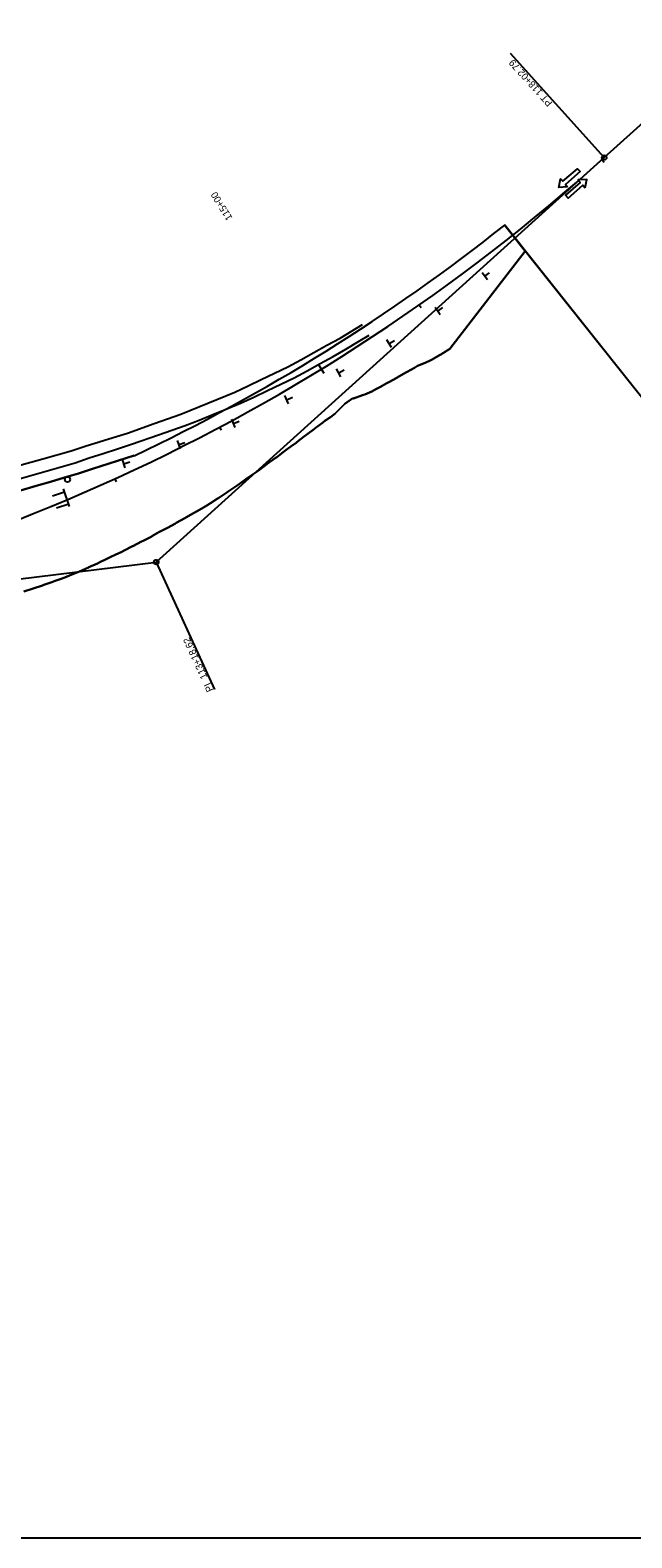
# Model space of a CAD drawing. Extents: x 1568809 to 1572786, y 728326 to 734907.
# Drawn here: x 1571487 to 1572002, y 731509 to 732799 of the extents above; entities that cross this region are included whole.
import ezdxf

# ---------------------------------------------------------------- set-up
doc = ezdxf.new("R2010")
doc.units = 0
for name, color, linetype in [('R_Horz Alg', 7, 'Continuous'), ('R_Horz Alg Annot', 7, 'Continuous'), ('R_MOT', 7, 'Continuous'), ('R_No Plot', 7, 'Continuous'), ('R_Striping', 7, 'Continuous')]:
    doc.layers.add(name, color=color, linetype=linetype)

msp = doc.modelspace()

# ---------------------------------------------------------------- linework, layer by layer
at = {"layer": 'R_Horz Alg'}
msp.add_line((1571978.5, 732690.3), (1572468.4, 733132.6), dxfattribs=at)
msp.add_arc((1570881.5, 733905.4), 1637, 277.05, 312.0749, dxfattribs=at)
at = {"layer": 'R_Horz Alg Annot'}
for p, q in [((1571595, 732344.1), (1571978.5, 732690.3)), ((1571082.4, 732280.7), (1571595, 732344.1))]:
    msp.add_line(p, q, dxfattribs=at)
for points in [[(1571978.5, 732690.3), (1571898.1, 732779.3)], [(1571978.4, 732686.2), (1571976.4, 732688.4)], [(1571901.9, 732621.5), (1571900.1, 732623.8)], [(1571821.6, 732561.6), (1571819.9, 732564)], [(1571734.2, 732512.7), (1571738.4, 732505.8)], [(1571650.9, 732457), (1571649.5, 732459.7)], [(1571561, 732412.8), (1571559.8, 732415.5)], [(1571595, 732344.1), (1571644.9, 732235)]]:
    msp.add_lwpolyline(points, dxfattribs=at)
for centre in [(1571978.5, 732690.3), (1571595, 732344.1)]:
    msp.add_circle(centre, 2, dxfattribs=at)
at = {"layer": 'R_MOT'}
for p, q in [((1571878.4, 732585.6), (1571873.8, 732591.7)), ((1571876.2, 732588.7), (1571880.3, 732591.8)), ((1571838, 732555.8), (1571833.6, 732562.1)), ((1571835.9, 732559), (1571840.2, 732562)), ((1571796.3, 732527.9), (1571792.3, 732534.4)), ((1571794.4, 732531.2), (1571798.9, 732533.9)), ((1571752.9, 732502.7), (1571749.3, 732509.4)), ((1571751.2, 732506.1), (1571755.8, 732508.6)), ((1571708.3, 732479.6), (1571705.1, 732486.6)), ((1571706.8, 732483.1), (1571711.5, 732485.3)), ((1571662.5, 732459.2), (1571659.6, 732466.3)), ((1571661.1, 732462.7), (1571666, 732464.7)), ((1571615.7, 732441), (1571613.2, 732448.2)), ((1571614.5, 732444.7), (1571619.5, 732446.4)), ((1571568.3, 732424.7), (1571566, 732431.9)), ((1571567.3, 732428.3), (1571572.3, 732429.9)), ((1571520.8, 732391.6), (1571515.7, 732406.7)), ((1571506.2, 732400.8), (1571516.5, 732404.3)), ((1571509.7, 732390.6), (1571520, 732394.1))]:
    msp.add_line(p, q, dxfattribs=at)
for points in [[(1571947, 732665.3), (1571939.7, 732664.8), (1571941.1, 732672.1), (1571943, 732670), (1571955.5, 732680.8), (1571957.7, 732678.3), (1571945.2, 732667.4)], [(1571962, 732664.5), (1571963.4, 732671.7), (1571956, 732671.2), (1571957.9, 732669.1), (1571945.4, 732658.3), (1571947.6, 732655.7), (1571960.1, 732666.6)]]:
    msp.add_lwpolyline(points, close=True, dxfattribs=at)
msp.add_circle((1571519, 732414.9), 2.25, dxfattribs=at)
at = {"layer": 'R_No Plot'}
for p, q in [((1572786.1, 731508.9), (1571892.9, 732632.9)), ((1572786.1, 731508.9), (1571893.2, 732632.4)), ((1571893.2, 732632.4), (1571905.7, 732616.7)), ((1571905.7, 732616.7), (1571893.2, 732632.4)), ((1571905.7, 732616.7), (1571910.8, 732610.2)), ((1571910.8, 732610.2), (1571905.7, 732616.7)), ((1571910.8, 732610.2), (1571846.2, 732526.5)), ((1571846.2, 732526.5), (1571910.8, 732610.2)), ((1569203.7, 731508.9), (1572786.1, 731508.9)), ((1569203.7, 731508.9), (1572786.1, 731508.9))]:
    msp.add_line(p, q, dxfattribs=at)
for points in [[(1571846.2, 732526.5), (1571838.5, 732521.8), (1571837.4, 732521.1), (1571831.2, 732517.6), (1571828.4, 732516.1), (1571823.6, 732514), (1571818.7, 732512), (1571815.9, 732510.4), (1571809.8, 732507), (1571808.6, 732506.3), (1571801.3, 732502.2), (1571800.8, 732501.9), (1571794.1, 732498.1), (1571791.9, 732496.9), (1571786.8, 732494.1), (1571782.9, 732492), (1571779.4, 732490.1), (1571773.5, 732487.6), (1571771.6, 732486.9), (1571763.7, 732484), (1571763.3, 732484.5)], [(1571763.3, 732484.5), (1571763.7, 732484), (1571771.6, 732486.9), (1571773.5, 732487.6), (1571779.4, 732490.1), (1571782.9, 732492), (1571786.8, 732494.1), (1571791.9, 732496.9), (1571794.1, 732498.1), (1571800.8, 732501.9), (1571801.3, 732502.2), (1571808.6, 732506.3), (1571809.8, 732507), (1571815.9, 732510.4), (1571818.7, 732512), (1571823.6, 732514), (1571828.4, 732516.1), (1571831.2, 732517.6), (1571837.4, 732521.1), (1571838.5, 732521.8), (1571846.2, 732526.5)], [(1571763.3, 732484.5), (1571756.5, 732479.7), (1571755.2, 732478.4), (1571750.4, 732473.6), (1571747.7, 732471), (1571744, 732468.2), (1571739.4, 732465), (1571737.2, 732463.4), (1571731.1, 732458.8), (1571730.5, 732458.3), (1571723.8, 732453.3), (1571722.9, 732452.6), (1571717.1, 732448.2), (1571714.6, 732446.3), (1571710.3, 732443.1), (1571706.3, 732440.2), (1571703.6, 732438.1), (1571698.1, 732433.9), (1571696.8, 732433), (1571690, 732428.2), (1571689.6, 732427.9), (1571683.2, 732423.1), (1571681.3, 732421.7), (1571676.3, 732418.1), (1571672.8, 732415.8), (1571669.4, 732413.3), (1571664.3, 732409.7), (1571662.5, 732408.5), (1571655.7, 732403.9), (1571655.5, 732403.8), (1571648.4, 732399.2), (1571647, 732398.3), (1571641.3, 732394.6), (1571638.3, 732392.6), (1571634.1, 732390.1), (1571629.4, 732387.3), (1571626.8, 732385.9), (1571620.3, 732382.3), (1571619.4, 732381.8), (1571612.1, 732377.7), (1571611.3, 732377.2), (1571604.7, 732373.5), (1571602.2, 732372.2), (1571597.3, 732369.6), (1571593.1, 732367.3), (1571589.9, 732365.5), (1571583.9, 732362.4), (1571582.4, 732361.6), (1571574.9, 732357.7), (1571574.7, 732357.6), (1571567.4, 732353.9), (1571565.5, 732352.9), (1571559.8, 732350.2), (1571556.1, 732348.5), (1571552.2, 732346.5), (1571546.8, 732343.9), (1571544.6, 732342.9), (1571537.3, 732339.7), (1571536.9, 732339.5), (1571529.2, 732336.1), (1571527.8, 732335.5), (1571521.4, 732332.8), (1571518.2, 732331.5), (1571513.5, 732329.8), (1571508.5, 732328), (1571505.5, 732327), (1571498.7, 732324.6), (1571497.6, 732324.2), (1571489.6, 732321.6), (1571488.8, 732321.3), (1571481.5, 732319)], [(1571481.5, 732319), (1571488.8, 732321.3), (1571489.6, 732321.6), (1571497.6, 732324.2), (1571498.7, 732324.6), (1571505.5, 732327), (1571508.5, 732328), (1571513.5, 732329.8), (1571518.2, 732331.5), (1571521.4, 732332.8), (1571527.8, 732335.5), (1571529.2, 732336.1), (1571536.9, 732339.5), (1571537.3, 732339.7), (1571544.6, 732342.9), (1571546.8, 732343.9), (1571552.2, 732346.5), (1571556.1, 732348.5), (1571559.8, 732350.2), (1571565.5, 732352.9), (1571567.4, 732353.9), (1571574.7, 732357.6), (1571574.9, 732357.7), (1571582.4, 732361.6), (1571583.9, 732362.4), (1571589.9, 732365.5), (1571593.1, 732367.3), (1571597.3, 732369.6), (1571602.2, 732372.2), (1571604.7, 732373.5), (1571611.3, 732377.2), (1571612.1, 732377.7), (1571619.4, 732381.8), (1571620.3, 732382.3), (1571626.8, 732385.9), (1571629.4, 732387.3), (1571634.1, 732390.1), (1571638.3, 732392.6), (1571641.3, 732394.6), (1571647, 732398.3), (1571648.4, 732399.2), (1571655.5, 732403.8), (1571655.7, 732403.9), (1571662.5, 732408.5), (1571664.3, 732409.7), (1571669.4, 732413.3), (1571672.8, 732415.8), (1571676.3, 732418.1), (1571681.3, 732421.7), (1571683.2, 732423.1), (1571689.6, 732427.9), (1571690, 732428.2), (1571696.8, 732433), (1571698.1, 732433.9), (1571703.6, 732438.1), (1571706.3, 732440.2), (1571710.3, 732443.1), (1571714.6, 732446.3), (1571717.1, 732448.2), (1571722.9, 732452.6), (1571723.8, 732453.3), (1571730.5, 732458.3), (1571731.1, 732458.8), (1571737.2, 732463.4), (1571739.4, 732465), (1571744, 732468.2), (1571747.7, 732471), (1571750.4, 732473.6), (1571755.2, 732478.4), (1571756.5, 732479.7), (1571763.3, 732484.5)], [(1571469.4, 732396.8), (1571455.4, 732432.3), (1571466.5, 732436.7), (1571478.9, 732405.4), (1571492.3, 732409.3), (1571504.4, 732412.9), (1571516.4, 732416.4), (1571528.5, 732419.9), (1571540.5, 732423.8), (1571576, 732435.2)], [(1571576, 732435.2), (1571540.5, 732423.8), (1571528.5, 732419.9), (1571516.4, 732416.4), (1571504.4, 732412.9), (1571492.3, 732409.3), (1571478.9, 732405.4), (1571466.5, 732436.7), (1571455.4, 732432.3), (1571469.4, 732396.8)], [(1571576, 732435.2), (1571540.5, 732423.8), (1571528.5, 732419.9), (1571516.4, 732416.4), (1571504.4, 732412.9), (1571492.3, 732409.3), (1571478.9, 732405.4)]]:
    msp.add_lwpolyline(points, dxfattribs=at)
msp.add_arc((1570881.5, 733905.4), 1626, 295.2862, 308.4772, dxfattribs=at)
msp.add_arc((1570881.5, 733905.4), 1626, 295.2862, 308.4772, dxfattribs=at)
msp.add_arc((1570881.5, 733905.4), 1626, 295.2862, 308.4772, dxfattribs=at)
at = {"layer": 'R_Striping'}
for points in [[(1571474.1, 732425.8), (1571498, 732432.6), (1571522, 732439.4), (1571534, 732443.2), (1571546.1, 732447), (1571558.2, 732450.8), (1571570.3, 732454.5), (1571593.2, 732462.6), (1571616.1, 732470.8), (1571639.1, 732480.1), (1571662.1, 732489.5), (1571673.5, 732494.9), (1571684.8, 732500.3), (1571696.2, 732505.7), (1571707.5, 732511.1), (1571718.7, 732517.3), (1571729.9, 732523.5), (1571741.1, 732529.7), (1571752.3, 732535.9), (1571771.5, 732547.5)], [(1571477.5, 732415.4), (1571501.5, 732422.3), (1571525.5, 732429.2), (1571537.6, 732433.2), (1571549.6, 732437.1), (1571561.7, 732441.1), (1571573.8, 732445.1), (1571596.8, 732453), (1571619.7, 732460.9), (1571631.6, 732465.7), (1571643.4, 732470.5), (1571655.3, 732475.2), (1571667.1, 732480), (1571678.6, 732485.4), (1571690.1, 732490.9), (1571701.6, 732496.3), (1571713.1, 732501.7), (1571724.1, 732507.9), (1571735.2, 732514.1), (1571746.3, 732520.2), (1571757.3, 732526.4), (1571768.2, 732533), (1571777.1, 732538.3)]]:
    msp.add_lwpolyline(points, dxfattribs=at)

# ---------------------------------------------------------------- texts
at = {"layer": 'R_Horz Alg Annot'}
for s, rotation, p in [('PT 118+02.79', 132.0749, (1571934.6, 732737.4)), ('115+00', 121.4772, (1571660.5, 732638.7)), ('PI  113+18.62', 114.5625, (1571644, 732234.6))]:
    msp.add_text(s, height=6, rotation=rotation, dxfattribs=at).set_placement(p)

doc.saveas('drawing.dxf')
